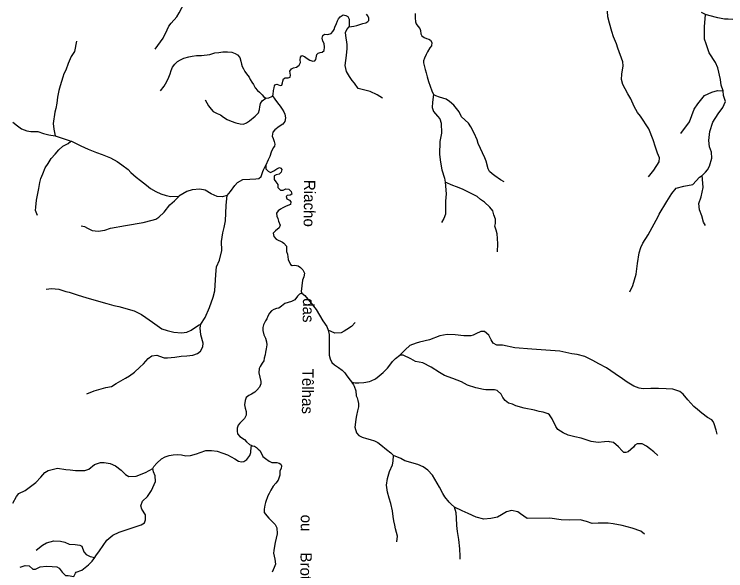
# Model space of a CAD drawing. Extents: x 717.8 to 772.7, y 8672.2 to 8728.
# Drawn here: x 746.93 to 759.54, y 8684.01 to 8693.87 of the extents above; entities that cross this region are included whole.
import ezdxf
from ezdxf.enums import TextEntityAlignment as Align

# ---------------------------------------------------------------- set-up
doc = ezdxf.new("R2010")
doc.units = 0
doc.header["$LTSCALE"] = 0.08
doc.linetypes.add('LONG_DASHED', pattern=[7.5, 6, -1.5])
doc.layers.add('61', color=7, linetype='Continuous')
doc.layers.add('9', color=7, linetype='LONG_DASHED', lineweight=25)

msp = doc.modelspace()

# ---------------------------------------------------------------- linework, layer by layer
at = {"layer": '9'}
for points in [[(749.4272, 8693.2486), (749.5689, 8693.4428), (749.6447, 8693.5956), (749.6705, 8693.6569), (749.7134, 8693.7126), (749.8131, 8693.8219), (749.8517, 8693.8942), (749.9082, 8693.996), (749.9669, 8694.0547), (750.0286, 8694.1045), (750.0941, 8694.1337), (750.1458, 8694.1889), (750.1965, 8694.2829), (750.2358, 8694.335), (750.3503, 8694.4356), (750.4211, 8694.4779), (750.5121, 8694.5363), (750.5579, 8694.5592)], [(751.5057, 8692.4242), (751.5206, 8692.4482), (751.527, 8692.5192), (751.5348, 8692.5652), (751.5419, 8692.601), (751.5598, 8692.623), (751.582, 8692.6319), (751.6432, 8692.6053), (751.6725, 8692.6106), (751.6874, 8692.6537), (751.6897, 8692.6823), (751.7017, 8692.7233), (751.7326, 8692.742), (751.7869, 8692.7419), (751.8214, 8692.7552), (751.8279, 8692.7875), (751.8183, 8692.8233), (751.8158, 8692.8638), (751.8419, 8692.9051), (751.8782, 8692.9202), (751.9323, 8692.9291), (751.9825, 8692.9666), (752.001, 8693.0133), (751.9985, 8693.061), (752.0008, 8693.1087), (752.029, 8693.1367), (752.0733, 8693.1207), (752.12, 8693.0826), (752.1677, 8693.0587), (752.2223, 8693.0391), (752.2596, 8693.0453), (752.2773, 8693.0683), (752.2796, 8693.0994), (752.2933, 8693.1543), (752.3163, 8693.18), (752.3533, 8693.1901), (752.389, 8693.1997), (752.4199, 8693.2283), (752.4298, 8693.2873), (752.421, 8693.3539), (752.4005, 8693.3906), (752.3846, 8693.4444), (752.3979, 8693.4949), (752.4289, 8693.5136), (752.4884, 8693.51), (752.5442, 8693.5287), (752.5783, 8693.5642), (752.5996, 8693.5976), (752.6138, 8693.6429), (752.6409, 8693.7052), (752.6604, 8693.754), (752.679, 8693.7886), (752.7083, 8693.8241), (752.7588, 8693.856), (752.8038, 8693.8482), (752.8413, 8693.8312), (752.867, 8693.7815), (752.8635, 8693.7242), (752.8674, 8693.6461)], [(752.8674, 8693.6461), (752.947, 8693.6574), (752.9992, 8693.6706), (753.0541, 8693.6848), (753.108, 8693.7048), (753.158, 8693.7192), (753.1949, 8693.7389), (753.2154, 8693.7603), (753.2125, 8693.8003), (753.1958, 8693.8385), (753.172, 8693.8718)], [(754.0327, 8693.8816), (754.0328, 8693.8041), (754.0428, 8693.7357), (754.0536, 8693.698), (754.082, 8693.6566), (754.1141, 8693.6183), (754.1279, 8693.5835), (754.1363, 8693.5222), (754.1551, 8693.4876), (754.1927, 8693.4594), (754.2343, 8693.4421), (754.2755, 8693.4266), (754.3056, 8693.4126), (754.3285, 8693.3697), (754.3249, 8693.3118), (754.2946, 8693.2723), (754.2505, 8693.2033), (754.2282, 8693.1572), (754.1975, 8693.0928), (754.1847, 8693.0462), (754.1823, 8693.0065), (754.2132, 8692.8935), (754.2261, 8692.834), (754.2468, 8692.7589), (754.2701, 8692.6761), (754.3282, 8692.5104), (754.3597, 8692.4449)], [(758.167, 8690.9924), (758.2631, 8691.1064), (758.3569, 8691.2562), (758.3616, 8691.3253), (758.3243, 8691.4083), (758.2879, 8691.5169), (758.2498, 8691.6465), (758.173, 8691.8412), (758.0239, 8692.0616), (757.9704, 8692.1314), (757.913, 8692.2377), (757.8511, 8692.3718), (757.7991, 8692.4595), (757.7557, 8692.5472), (757.713, 8692.6278), (757.6899, 8692.7148), (757.6953, 8692.8087), (757.7169, 8692.9537), (757.7105, 8693.0275), (757.6257, 8693.2674), (757.602, 8693.344), (757.5446, 8693.472), (757.516, 8693.5658), (757.4733, 8693.7093), (757.4485, 8693.8234), (757.44, 8693.9226)], [(759.1758, 8693.8676), (759.103, 8693.8979)], [(759.4919, 8692.5149), (759.4537, 8692.6122), (759.4446, 8692.7129), (759.3925, 8692.9213), (759.3562, 8693.0133), (759.243, 8693.1877), (759.186, 8693.3475), (759.1594, 8693.4275), (759.1608, 8693.6483), (759.1758, 8693.8676)], [(759.8242, 8693.7799), (759.7633, 8693.7765), (759.6609, 8693.776), (759.5764, 8693.7799), (759.5107, 8693.782), (759.3954, 8693.8049), (759.2377, 8693.8445), (759.1758, 8693.8676)], [(753.4534, 8692.3807), (753.3585, 8692.4419), (753.2352, 8692.5014), (753.167, 8692.5181), (753.0276, 8692.5555), (752.9593, 8692.6477), (752.9185, 8692.6983), (752.8698, 8692.7693), (752.8192, 8692.8571), (752.7916, 8692.9609), (752.8156, 8693.1375), (752.8316, 8693.2608), (752.8292, 8693.335), (752.8085, 8693.4923), (752.8032, 8693.5455), (752.8236, 8693.597), (752.8674, 8693.6461)], [(748.0371, 8693.3913), (747.9983, 8693.2076), (747.9428, 8693.1225), (747.8876, 8692.9981), (747.845, 8692.8792), (747.8118, 8692.8146), (747.7927, 8692.7524), (747.7477, 8692.6039), (747.7216, 8692.5196), (747.6997, 8692.4004), (747.6894, 8692.2932), (747.668, 8692.1996), (747.6552, 8692.1337), (747.6244, 8691.9343), (747.6354, 8691.835), (747.6605, 8691.7156)], [(749.521, 8692.5149), (749.5912, 8692.5947), (749.6388, 8692.6809), (749.6716, 8692.7528), (749.6929, 8692.8149), (749.7106, 8692.8725), (749.7363, 8692.9337), (749.778, 8692.9838), (749.8248, 8693.0307), (749.8762, 8693.0612), (749.9385, 8693.089), (750.0259, 8693.1175), (750.082, 8693.1246), (750.1592, 8693.1388), (750.2498, 8693.1396), (750.3961, 8693.1583), (750.4875, 8693.184), (750.5549, 8693.1946), (750.6303, 8693.2047), (750.7127, 8693.2036), (750.7845, 8693.1956), (750.8448, 8693.1752), (750.8856, 8693.1477), (750.9308, 8693.1024), (750.9495, 8693.0403), (750.9601, 8692.9844), (750.9707, 8692.9427), (750.9919, 8692.9018), (751.0177, 8692.8539), (751.0443, 8692.8167), (751.0913, 8692.7528), (751.1143, 8692.7164), (751.1436, 8692.6676), (751.1693, 8692.6254), (751.203, 8692.5683), (751.2438, 8692.5186), (751.2748, 8692.4884), (751.3236, 8692.4397), (751.3493, 8692.4148), (751.39, 8692.3821)], [(758.7372, 8691.7573), (758.8927, 8691.9644), (758.9725, 8692.1869), (759.0403, 8692.2813), (759.1602, 8692.43), (759.2859, 8692.4874), (759.3913, 8692.521), (759.4919, 8692.5149)], [(759.1191, 8691.0103), (759.1742, 8691.0698), (759.2125, 8691.1149), (759.2462, 8691.1806), (759.2885, 8691.3224), (759.2828, 8691.4253), (759.2479, 8691.5192), (759.2371, 8691.6343), (759.2509, 8691.7948), (759.3087, 8691.9576), (759.4022, 8692.1026), (759.4841, 8692.219), (759.5327, 8692.322), (759.4944, 8692.4325), (759.4919, 8692.5149)], [(750.3161, 8692.3544), (750.3764, 8692.2444), (750.4189, 8692.1885), (750.4571, 8692.1477), (750.5253, 8692.1088), (750.5875, 8692.0874), (750.6401, 8692.0492), (750.7022, 8692.0039), (750.7763, 8691.9753), (750.8597, 8691.9472), (750.9342, 8691.9286), (750.991, 8691.9241), (751.0451, 8691.9472), (751.1012, 8691.9805), (751.2012, 8692.0634), (751.2588, 8692.1237), (751.2801, 8692.1841), (751.2827, 8692.2315), (751.297, 8692.2865), (751.3237, 8692.3358), (751.39, 8692.3821)], [(751.39, 8692.3821), (751.4419, 8692.3907), (751.4968, 8692.4099), (751.5057, 8692.4242)], [(751.5057, 8692.4242), (751.5488, 8692.3646), (751.5979, 8692.3014), (751.6423, 8692.2428), (751.6774, 8692.189), (751.7078, 8692.1397), (751.7264, 8692.0976), (751.7369, 8692.0369), (751.7241, 8691.971), (751.6926, 8691.9198), (751.6261, 8691.8795), (751.5501, 8691.8208), (751.5135, 8691.7797), (751.5011, 8691.7105), (751.5172, 8691.6706), (751.5359, 8691.6167), (751.5472, 8691.5703), (751.5405, 8691.5347), (751.5218, 8691.5041), (751.4815, 8691.4283), (751.4575, 8691.3511), (751.4309, 8691.2908), (751.3922, 8691.1951)], [(754.3597, 8692.4449), (754.3403, 8692.3136), (754.3366, 8692.2163), (754.359, 8692.1461), (754.431, 8692.0621), (754.4687, 8692.0143), (754.4923, 8691.9378), (754.5023, 8691.7612), (754.4707, 8691.6136), (754.4623, 8691.3852), (754.4838, 8691.2504), (754.5086, 8691.1117), (754.5512, 8690.9631), (754.5646, 8690.8945)], [(755.6131, 8690.8988), (755.5462, 8690.9358), (755.448, 8691.006), (755.3984, 8691.0402), (755.3506, 8691.086), (755.3275, 8691.1304), (755.2943, 8691.2699), (755.2657, 8691.3237), (755.1477, 8691.5807), (755.1294, 8691.6477), (755.0762, 8691.7654), (755.019, 8691.8746), (754.9759, 8691.9422), (754.8543, 8692.0545), (754.8111, 8692.1425), (754.7187, 8692.2618), (754.6433, 8692.3245), (754.5849, 8692.3657), (754.4654, 8692.4002), (754.4013, 8692.4221), (754.3597, 8692.4449)], [(746.9084, 8691.9583), (746.9889, 8691.893), (747.0598, 8691.8423), (747.1562, 8691.8031), (747.2288, 8691.794), (747.3497, 8691.7924), (747.4503, 8691.7596), (747.5473, 8691.7326), (747.6605, 8691.7156)], [(747.6605, 8691.7156), (747.8009, 8691.6664), (747.8884, 8691.6413), (747.9357, 8691.6236)], [(747.3439, 8690.3074), (747.3089, 8690.3935), (747.3142, 8690.454), (747.3265, 8690.5777), (747.3491, 8690.6929), (747.367, 8690.7853), (747.3897, 8690.8907), (747.4041, 8690.9624), (747.4394, 8691.0452), (747.4837, 8691.1492), (747.5337, 8691.2246), (747.5863, 8691.3124), (747.6564, 8691.3928), (747.7239, 8691.468), (747.7966, 8691.5321), (747.8899, 8691.578), (747.9357, 8691.6236)], [(747.9357, 8691.6236), (747.9484, 8691.6188), (748.0159, 8691.5861), (748.1109, 8691.5385), (748.2422, 8691.4813), (748.3886, 8691.4207), (748.4915, 8691.3843), (748.6373, 8691.3248), (748.7554, 8691.2599), (748.8407, 8691.2001), (748.9537, 8691.1206), (749.0001, 8691.0673), (749.0952, 8690.9821), (749.1702, 8690.922), (749.2739, 8690.8392), (749.3489, 8690.784), (749.4415, 8690.7314), (749.529, 8690.6863), (749.6216, 8690.6563), (749.7092, 8690.6387), (749.8504, 8690.6461)], [(750.7033, 8690.6564), (750.7615, 8690.7315), (750.8397, 8690.8355), (750.8852, 8690.8876), (750.9829, 8690.9396), (751.1064, 8690.9462), (751.2105, 8690.9529), (751.2637, 8690.9616), (751.3068, 8690.9942), (751.3341, 8691.0829), (751.3472, 8691.1154), (751.3922, 8691.1951)], [(751.3922, 8691.1951), (751.3917, 8691.1315), (751.4301, 8691.0903), (751.4709, 8691.0664), (751.5298, 8691.0967), (751.5819, 8691.1338), (751.6287, 8691.156), (751.6563, 8691.1414), (751.672, 8691.1217), (751.6603, 8691.072), (751.6237, 8691.0361), (751.5744, 8691.0224), (751.5346, 8691.0045), (751.5386, 8690.9443), (751.5668, 8690.9005), (751.6038, 8690.8515), (751.6037, 8690.7995), (751.6481, 8690.7549), (751.6958, 8690.7549), (751.7443, 8690.7768), (751.7991, 8690.769), (751.839, 8690.7314), (751.8476, 8690.6837), (751.8233, 8690.6633), (751.7669, 8690.6584), (751.7483, 8690.6399), (751.7584, 8690.6023), (751.8085, 8690.578), (751.8327, 8690.5467), (751.8234, 8690.5013), (751.7498, 8690.4677), (751.6888, 8690.4403), (751.6482, 8690.4153), (751.6075, 8690.3848), (751.5809, 8690.348), (751.584, 8690.2917), (751.5997, 8690.2525), (751.6138, 8690.2048), (751.6404, 8690.1312), (751.6248, 8690.0836), (751.5583, 8690.0318), (751.5207, 8689.9943), (751.5309, 8689.9316), (751.57, 8689.8839), (751.6834, 8689.8346), (751.7061, 8689.816), (751.7554, 8689.7625), (751.7546, 8689.6687), (751.7702, 8689.6217), (751.7851, 8689.5262), (751.8234, 8689.4346), (751.8547, 8689.4213), (751.9017, 8689.4268), (751.9642, 8689.4111), (752.0041, 8689.3822), (752.0469, 8689.3406), (752.0765, 8689.2812), (752.0596, 8689.221), (752.0369, 8689.1568), (752.0241, 8689.0581), (752.0135, 8688.9557), (752.0251, 8688.9302)], [(757.8385, 8688.9508), (757.8892, 8689.0648), (757.9467, 8689.2653), (757.9705, 8689.4541), (758.0008, 8689.6453), (758.0313, 8689.7369), (758.0686, 8689.8163), (758.1585, 8689.9602), (758.336, 8690.2845), (758.3574, 8690.3273), (758.4894, 8690.5553), (758.5775, 8690.6929), (758.6564, 8690.7877), (758.7895, 8690.8216), (758.9495, 8690.8543), (759.0681, 8690.9863), (759.1191, 8691.0103)], [(759.1745, 8690.1273), (759.1435, 8690.1865), (759.1125, 8690.3005), (759.0679, 8690.4049), (759.0569, 8690.5146), (759.0987, 8690.6342), (759.1333, 8690.7977), (759.1245, 8690.9457), (759.1191, 8691.0103)], [(754.5646, 8690.8945), (754.5859, 8690.6894), (754.5729, 8690.5594), (754.5727, 8690.3905), (754.5689, 8690.3276), (754.5427, 8690.2528), (754.4987, 8690.1779)], [(755.4953, 8689.6628), (755.5002, 8689.8017), (755.4931, 8689.8973), (755.4869, 8689.9794), (755.4691, 8690.0431), (755.4448, 8690.118), (755.4553, 8690.163), (755.4554, 8690.2371), (755.4292, 8690.3185), (755.4074, 8690.3875), (755.3587, 8690.4493), (755.263, 8690.5384), (755.1942, 8690.5861), (755.1341, 8690.6393), (755.0368, 8690.6908), (754.9807, 8690.717), (754.9194, 8690.7498), (754.8721, 8690.7684), (754.765, 8690.8142), (754.7009, 8690.8386), (754.5646, 8690.8945)], [(750.7033, 8690.6564), (750.6172, 8690.6355), (750.5279, 8690.6389), (750.4236, 8690.687), (750.3135, 8690.7512), (750.221, 8690.7684), (750.0839, 8690.7585), (749.9884, 8690.7276), (749.8504, 8690.6461)], [(748.1191, 8690.122), (748.1758, 8690.1124), (748.2304, 8690.0795), (748.3128, 8690.0408), (748.4175, 8690.026), (748.5351, 8690.0474), (748.6393, 8690.0799), (748.906, 8690.1286), (749.2184, 8690.1807), (749.3745, 8690.2229), (749.4417, 8690.2386), (749.4939, 8690.2769), (749.5897, 8690.3665), (749.6919, 8690.4916), (749.7722, 8690.5616), (749.8466, 8690.642), (749.8504, 8690.6461)], [(750.2363, 8688.3805), (750.3154, 8688.4979), (750.3937, 8688.6734), (750.459, 8688.8552), (750.4851, 8688.9722), (750.5019, 8689.2576), (750.515, 8689.3981), (750.5716, 8689.5158), (750.6099, 8689.6869), (750.6031, 8689.8441), (750.626, 8689.9977), (750.6496, 8690.0898), (750.676, 8690.2116), (750.6848, 8690.4839), (750.6997, 8690.603), (750.7033, 8690.6564)], [(747.4971, 8688.9985), (747.592, 8689.0096), (747.7232, 8688.9974), (747.8487, 8688.9595), (747.9045, 8688.9463), (748.0475, 8688.9009), (748.2165, 8688.8489), (748.5754, 8688.7482), (748.6963, 8688.71), (748.7834, 8688.692), (749.059, 8688.6131), (749.1865, 8688.5525), (749.2661, 8688.5002), (749.3831, 8688.4159), (749.5479, 8688.297), (749.6394, 8688.2659), (749.7587, 8688.2398), (749.8943, 8688.2257), (749.9891, 8688.2354), (750.0689, 8688.2734), (750.1982, 8688.3642), (750.2363, 8688.3805)], [(752.0251, 8688.9302), (751.9867, 8688.9133), (751.9517, 8688.8751), (751.9029, 8688.8107), (751.8453, 8688.7812), (751.7824, 8688.7613), (751.727, 8688.7441), (751.6641, 8688.6961), (751.62, 8688.6654), (751.5773, 8688.6557), (751.5294, 8688.6415), (751.4892, 8688.6167), (751.4546, 8688.5771), (751.4276, 8688.5194), (751.4066, 8688.4736), (751.3835, 8688.4364), (751.3459, 8688.3693), (751.3358, 8688.3191), (751.3334, 8688.2649), (751.3528, 8688.1931), (751.382, 8688.1317), (751.4025, 8688.0696), (751.405, 8688.0119), (751.3949, 8687.9416), (751.3824, 8687.8864), (751.3749, 8687.8388), (751.3626, 8687.7753), (751.3552, 8687.7319), (751.326, 8687.6862), (751.2899, 8687.6306), (751.2736, 8687.5919), (751.2683, 8687.5193), (751.286, 8687.44), (751.2985, 8687.3623), (751.3035, 8687.3221), (751.2785, 8687.2645), (751.2285, 8687.2118), (751.196, 8687.1741), (751.1335, 8687.139), (751.086, 8687.1139), (751.0435, 8687.0788), (751.021, 8687.0287), (751.0123, 8686.9534), (751.0248, 8686.8933), (751.0397, 8686.8356), (751.0408, 8686.7684), (751.0131, 8686.7108), (750.9742, 8686.6764), (750.9299, 8686.625), (750.8998, 8686.59), (750.8798, 8686.5374), (750.8798, 8686.4823), (750.8874, 8686.4396), (750.9275, 8686.3896), (751.01, 8686.337), (751.0488, 8686.2969), (751.1014, 8686.2493), (751.1385, 8686.2318)], [(752.0251, 8688.9302), (752.0815, 8688.8892), (752.1907, 8688.7498), (752.2814, 8688.6395), (752.4007, 8688.439), (752.4672, 8688.3396), (752.4928, 8688.2717)], [(748.219, 8687.1446), (748.3477, 8687.2001), (748.4313, 8687.2256), (748.5564, 8687.2588), (748.6553, 8687.2749), (748.7403, 8687.3295), (748.9029, 8687.4249), (748.9766, 8687.4658), (749.0611, 8687.5307), (749.1605, 8687.6193), (749.2242, 8687.6796), (749.307, 8687.7705), (749.3724, 8687.8206), (749.4606, 8687.8293), (749.5063, 8687.8135), (749.5885, 8687.7847), (749.6505, 8687.7836), (749.7795, 8687.7982), (749.8902, 8687.8113), (749.9877, 8687.8179), (750.0958, 8687.8291), (750.1774, 8687.863), (750.235, 8687.9024), (750.2728, 8687.9813), (750.2768, 8688.0422), (750.2391, 8688.1912), (750.2281, 8688.3142), (750.2363, 8688.3805)], [(752.9709, 8688.4093), (752.906, 8688.3388), (752.826, 8688.2826), (752.7793, 8688.2559), (752.7222, 8688.224), (752.6135, 8688.2222), (752.4928, 8688.2717)], [(752.4928, 8688.2717), (752.514, 8688.1991), (752.514, 8688.1239), (752.5114, 8688.0561), (752.5114, 8688.0059), (752.5089, 8687.9357), (752.5113, 8687.883), (752.5126, 8687.8318), (752.5259, 8687.7645), (752.5611, 8687.7025), (752.6081, 8687.658), (752.6746, 8687.6126), (752.7387, 8687.5648), (752.7856, 8687.5171), (752.8146, 8687.4811), (752.8792, 8687.3942), (752.913, 8687.3505)], [(759.3799, 8686.4294), (759.3627, 8686.5037), (759.3324, 8686.6122), (759.3114, 8686.6551), (759.2895, 8686.6862), (759.213, 8686.7258), (759.1096, 8686.804), (759.0356, 8686.8713), (758.9667, 8686.9201), (758.8632, 8687.0395), (758.7826, 8687.1425), (758.7242, 8687.1879), (758.5983, 8687.2299), (758.4777, 8687.2333), (758.3414, 8687.2397), (758.2083, 8687.2417), (758.0738, 8687.2316), (758.0015, 8687.2485), (757.9081, 8687.2821), (757.7887, 8687.3553), (757.7072, 8687.4142), (757.5735, 8687.5004), (757.4244, 8687.6041), (757.2883, 8687.6752), (757.1816, 8687.7375), (757.0419, 8687.8045), (756.9058, 8687.8432), (756.8086, 8687.8559), (756.5947, 8687.901), (756.2643, 8687.9264), (756.1024, 8687.9391), (755.7981, 8687.9582), (755.5814, 8688.0054), (755.4779, 8688.01), (755.4157, 8688.0434), (755.3808, 8688.1026), (755.3384, 8688.1856), (755.2627, 8688.2504), (755.1955, 8688.2529), (755.109, 8688.2063), (755.0592, 8688.1856), (755.0206, 8688.1721), (754.8936, 8688.1713), (754.7401, 8688.1931), (754.5992, 8688.1941), (754.4739, 8688.1731), (754.2873, 8688.1016), (754.1121, 8688.063), (754.0502, 8688.0461), (753.94, 8688.0023), (753.8596, 8687.9265), (753.7629, 8687.8325)], [(752.913, 8687.3505), (752.9718, 8687.3394), (753.0344, 8687.3379), (753.1275, 8687.3457), (753.2245, 8687.3637), (753.2565, 8687.3778), (753.3316, 8687.4125), (753.3988, 8687.4627), (753.4671, 8687.5218), (753.5419, 8687.5995), (753.5866, 8687.6556), (753.6319, 8687.7186), (753.6837, 8687.7746), (753.7629, 8687.8325)], [(758.3332, 8686.0511), (758.2617, 8686.1158), (758.1838, 8686.1806), (758.1291, 8686.2175), (758.0568, 8686.2587), (757.9651, 8686.262), (757.9256, 8686.2368), (757.8986, 8686.1997), (757.8062, 8686.1182), (757.7667, 8686.1073), (757.7322, 8686.1089), (757.6977, 8686.1347), (757.6365, 8686.2093), (757.5465, 8686.2859), (757.4759, 8686.2985), (757.4642, 8686.3028), (757.3864, 8686.2962), (757.2762, 8686.2831), (757.1531, 8686.3023), (756.9746, 8686.3583), (756.8614, 8686.3861), (756.8161, 8686.3989), (756.7414, 8686.4157), (756.6538, 8686.4569), (756.5633, 8686.5153), (756.524, 8686.5677), (756.4601, 8686.7048), (756.414, 8686.7741), (756.3881, 8686.7935), (756.3006, 8686.822), (756.2294, 8686.8349), (756.1452, 8686.8543), (755.9641, 8686.8927), (755.8148, 8686.9315), (755.7575, 8686.96), (755.6887, 8686.9827), (755.6285, 8687.0257), (755.5885, 8687.0814), (755.558, 8687.1385), (755.4876, 8687.2043), (755.4398, 8687.2183), (755.2837, 8687.2162), (755.2448, 8687.2227), (755.1113, 8687.2544), (754.9619, 8687.2974), (754.8564, 8687.3586), (754.701, 8687.4169), (754.5552, 8687.4687), (754.4676, 8687.5219), (754.319, 8687.6178), (754.1679, 8687.6963), (754.0412, 8687.7214), (753.9551, 8687.7636), (753.8237, 8687.8333), (753.7629, 8687.8325)], [(752.913, 8687.3505), (752.9141, 8687.3491), (752.9445, 8687.3066), (752.956, 8687.2845), (752.9815, 8687.1987), (752.9909, 8687.1119), (753.0058, 8687.0727), (753.0214, 8687.0282), (753.0293, 8686.9771), (753.0277, 8686.9148), (753.014, 8686.8428), (752.9978, 8686.7627), (752.9854, 8686.695), (752.9779, 8686.6424), (752.968, 8686.5548), (752.9923, 8686.4578), (753.0361, 8686.409), (753.0975, 8686.3762), (753.1748, 8686.3535), (753.2399, 8686.3395), (753.3147, 8686.3119), (753.3721, 8686.282), (753.427, 8686.2444), (753.5254, 8686.1591), (753.6003, 8686.1019), (753.651, 8686.056)], [(749.3902, 8685.8222), (749.4085, 8685.859), (749.456, 8685.9191), (749.5444, 8685.9967), (749.6069, 8686.0293), (749.677, 8686.0518), (749.7475, 8686.0675), (749.8221, 8686.0695), (749.8972, 8686.067), (749.9698, 8686.0495), (750.0548, 8686.0546), (750.1625, 8686.0822), (750.2275, 8686.1073), (750.3276, 8686.1399), (750.4277, 8686.145), (750.5266, 8686.1322), (750.6294, 8686.0979), (750.7129, 8686.065), (750.7749, 8686.0287), (750.8406, 8685.993), (750.9067, 8685.9533), (750.9586, 8685.939), (751.0023, 8685.9469), (751.0513, 8685.9851), (751.1035, 8686.0546), (751.125, 8686.1085), (751.1324, 8686.207), (751.1385, 8686.2318)], [(751.1385, 8686.2318), (751.1489, 8686.2269), (751.1914, 8686.2168), (751.2239, 8686.1943), (751.2564, 8686.1668), (751.2849, 8686.1409), (751.3168, 8686.0748), (751.3373, 8686.038), (751.3844, 8685.9983), (751.4456, 8685.9557), (751.4957, 8685.9307), (751.5825, 8685.9282), (751.627, 8685.9199), (751.6565, 8685.9016), (751.6697, 8685.8689), (751.6628, 8685.8244), (751.6383, 8685.7793), (751.6375, 8685.7073), (751.6066, 8685.6191), (751.568, 8685.5666), (751.5181, 8685.5108), (751.4807, 8685.4407), (751.4486, 8685.3813), (751.4251, 8685.3372), (751.3839, 8685.2196), (751.3709, 8685.1752), (751.358, 8685.1018), (751.3598, 8685.0456), (751.4042, 8684.9824), (751.4422, 8684.9451), (751.4926, 8684.8951), (751.5575, 8684.8301), (751.5834, 8684.7711), (751.5879, 8684.6633), (751.5725, 8684.5873), (751.5569, 8684.513), (751.5426, 8684.4473), (751.5301, 8684.3722), (751.5272, 8684.3211), (751.5517, 8684.2168), (751.5589, 8684.1293), (751.5389, 8684.0721), (751.5213, 8684.0271), (751.5013, 8683.9845)], [(753.7103, 8684.5227), (753.7233, 8684.6247), (753.6844, 8684.7542), (753.6728, 8684.8217), (753.6559, 8684.8942), (753.645, 8684.9753), (753.6324, 8685.0714), (753.6019, 8685.204), (753.5758, 8685.2957), (753.5413, 8685.4042), (753.5272, 8685.5297), (753.5456, 8685.6483), (753.5818, 8685.7686), (753.6306, 8685.8872), (753.6446, 8685.9524), (753.651, 8686.056)], [(754.7334, 8685.1374), (754.6731, 8685.1917), (754.6361, 8685.2254), (754.5588, 8685.3238), (754.5218, 8685.3827), (754.4625, 8685.4933), (754.3393, 8685.7066), (754.2578, 8685.7932), (754.1779, 8685.8521), (754.0803, 8685.8958), (753.8525, 8685.9589), (753.781, 8686.0035), (753.651, 8686.056)], [(746.9074, 8685.2087), (746.9706, 8685.3283), (747.0121, 8685.3803), (747.1254, 8685.4311), (747.2467, 8685.5215), (747.3157, 8685.5748), (747.4066, 8685.672), (747.4779, 8685.7497), (747.5363, 8685.7886), (747.6987, 8685.8275), (747.8481, 8685.8081), (747.926, 8685.8016), (748.017, 8685.7887), (748.1827, 8685.7879), (748.2545, 8685.8139), (748.3549, 8685.8925), (748.4601, 8685.9291), (748.5238, 8685.9314), (748.6312, 8685.9119), (748.7266, 8685.8691), (748.8264, 8685.7924), (748.9067, 8685.7174), (748.9629, 8685.6835), (749.0957, 8685.6871), (749.2588, 8685.7503), (749.3902, 8685.8222)], [(748.3582, 8684.2497), (748.3807, 8684.2762), (748.4457, 8684.3668), (748.5755, 8684.5556), (748.6814, 8684.645), (748.7932, 8684.6983), (748.9353, 8684.7449), (749.0767, 8684.7909), (749.1807, 8684.8268), (749.2378, 8684.8639), (749.2588, 8684.9159), (749.2555, 8685.0027), (749.1911, 8685.1014), (749.1727, 8685.1613), (749.2043, 8685.2461), (749.2944, 8685.327), (749.3628, 8685.4356), (749.4338, 8685.592), (749.4265, 8685.6946), (749.4009, 8685.7656), (749.3902, 8685.8222)], [(754.8321, 8684.2203), (754.831, 8684.27), (754.8244, 8684.3995), (754.805, 8684.5678), (754.7824, 8684.7066), (754.774, 8684.8118), (754.7659, 8684.9497), (754.7593, 8685.0403), (754.7334, 8685.1374)], [(758.0986, 8684.6595), (758.0287, 8684.7142), (757.8796, 8684.7659), (757.7001, 8684.8142), (757.5425, 8684.8431), (757.4517, 8684.856), (757.2768, 8684.8557), (757.1669, 8684.8488), (757.0694, 8684.8858), (756.9535, 8684.9125), (756.7684, 8684.907), (756.6204, 8684.9129), (756.4204, 8684.9424), (756.0151, 8684.9367), (755.9003, 8685.0226), (755.855, 8685.0549), (755.7426, 8685.0814), (755.6518, 8685.0553), (755.5652, 8685.0049), (755.492, 8684.9629), (755.3718, 8684.9351), (755.2515, 8684.9267), (755.1153, 8684.9604), (754.9749, 8685.0235), (754.8673, 8685.0739), (754.7334, 8685.1374)], [(747.3246, 8684.3766), (747.4315, 8684.4683), (747.5054, 8684.5091), (747.6321, 8684.5406), (747.7521, 8684.538), (747.8287, 8684.5157), (747.9045, 8684.4847), (748.013, 8684.4779), (748.0951, 8684.464), (748.1308, 8684.4449), (748.1653, 8684.3502), (748.2079, 8684.2985), (748.2795, 8684.2656), (748.3582, 8684.2497)], [(747.9871, 8683.9127), (748.0181, 8683.9702), (748.0304, 8683.9902), (748.13, 8684.0255), (748.1919, 8684.072), (748.2482, 8684.1178), (748.3151, 8684.1841), (748.3582, 8684.2497)], [(747.0401, 8684.0733), (747.1272, 8684.1077), (747.1986, 8684.1012), (747.2623, 8684.0398), (747.3076, 8684.0388), (747.3933, 8684.0801), (747.5021, 8684.0943), (747.6076, 8684.0884), (747.6855, 8684.0801), (747.7289, 8684.0559), (747.7833, 8683.9844), (747.8407, 8683.9305), (747.8869, 8683.9267), (747.9871, 8683.9127)]]:
    msp.add_lwpolyline(points, dxfattribs=at)

# ---------------------------------------------------------------- texts
at = {"layer": '61'}
msp.add_text('Riacho                 das           Têlhas                        ou     Brotas', height=0.2, rotation=269.449, dxfattribs=at).set_placement((752.032, 8687.2507), align=Align.CENTER)

doc.saveas('drawing.dxf')
